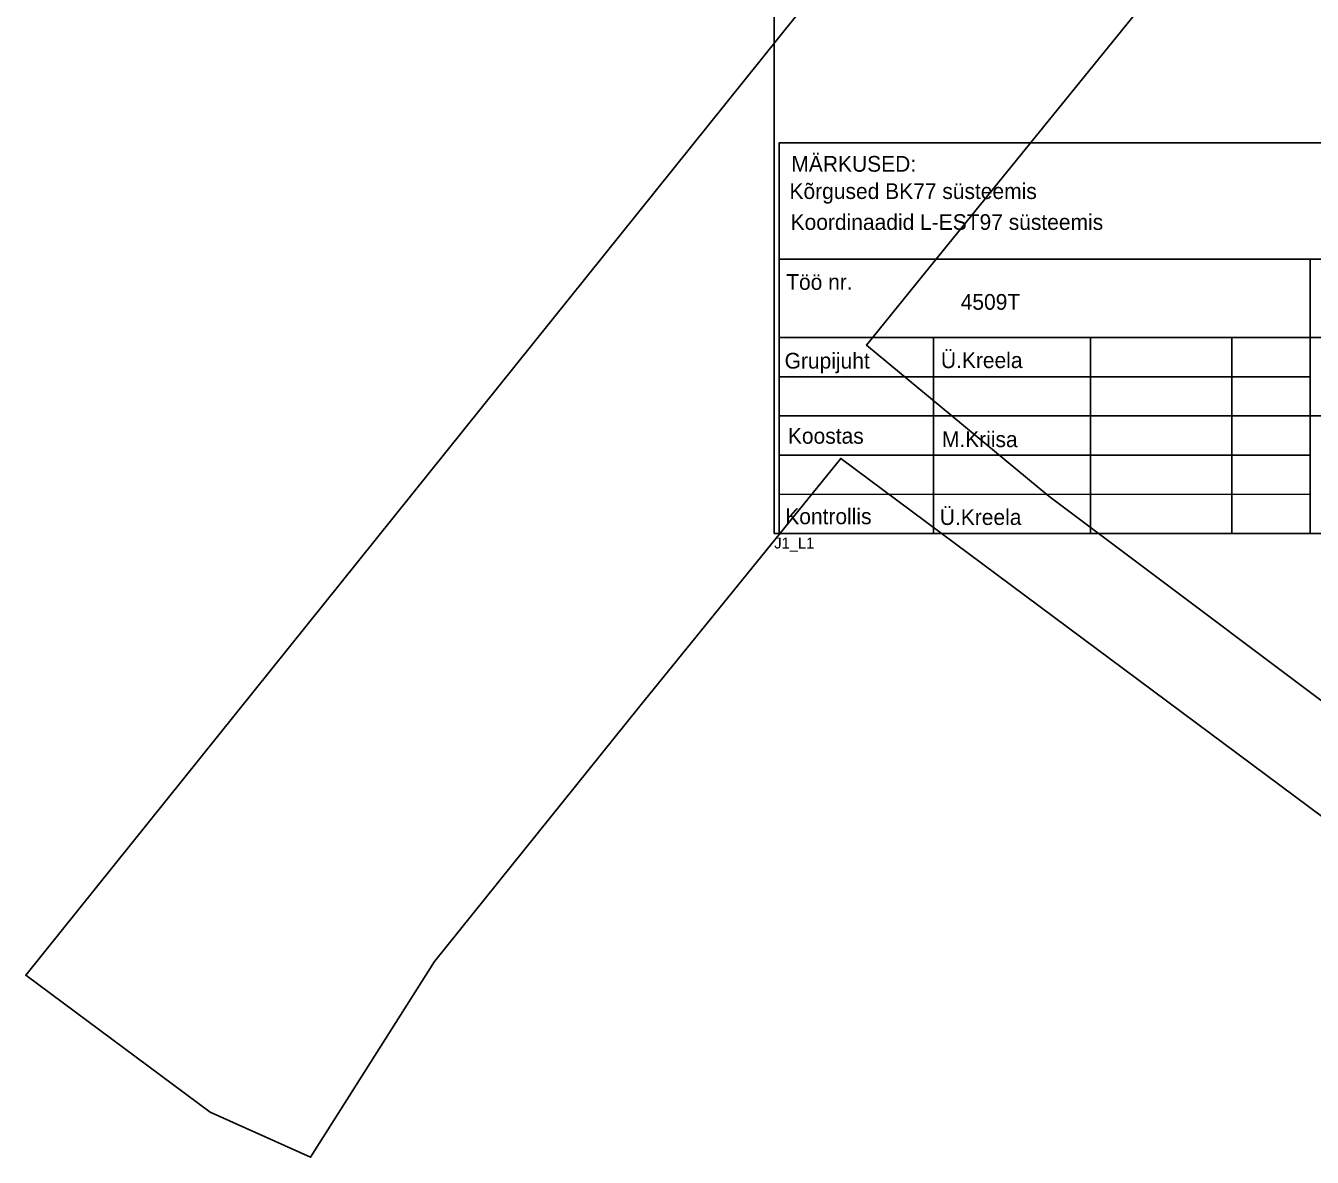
# Model space of a CAD drawing. Extents: x 640876 to 641182, y 6455704 to 6455993.
# Drawn here: x 640876.4 to 640958.4, y 6455746.4 to 6455818.5 of the extents above; entities that cross this region are included whole.
import ezdxf

# ---------------------------------------------------------------- set-up
doc = ezdxf.new("R2010")
doc.units = 0
doc.layers.add('PIIR', color=7, linetype='Continuous')
doc.layers.add('VORMISTUS', color=7, linetype='Continuous')

msp = doc.modelspace()

# ---------------------------------------------------------------- linework, layer by layer
at = {"layer": 'PIIR'}
msp.add_lwpolyline([(641037.5, 6455958.58), (641024.93, 6455943.02), (641012.36, 6455927.46), (640993.57, 6455904.12), (640971.01, 6455875.38), (640962.33, 6455865.02), (640876.41, 6455757.97), (640888.17, 6455749.25), (640894.56, 6455746.37), (640902.45, 6455758.84), (640915.55, 6455775.13), (640928.34, 6455790.92), (640960.9, 6455766.7), (640964.64, 6455771.22), (640941.6, 6455788.51), (640929.99, 6455798.13), (640933.13, 6455802.02), (640952.64, 6455826.1), (640977.72, 6455857.07), (640984.64, 6455865.92), (641005.01, 6455891.09), (641032.25, 6455870.2), (641049.71, 6455856.81)], dxfattribs=at)
at = {"layer": 'VORMISTUS'}
for p, q in [((640924.41, 6455803.627), (641016.602, 6455803.627)), ((640924.41, 6455803.627), (640924.416, 6455786.126)), ((640958.259, 6455803.62), (640958.262, 6455786.129)), ((640924.411, 6455798.631), (641016.602, 6455798.621)), ((640934.257, 6455798.63), (640934.262, 6455786.126)), ((640944.262, 6455798.624), (640944.264, 6455786.129)), ((640953.263, 6455798.623), (640953.256, 6455786.125)), ((640924.412, 6455796.128), (640958.258, 6455796.13)), ((640924.414, 6455793.625), (640991.762, 6455793.625)), ((640924.413, 6455791.132), (640958.261, 6455791.125)), ((640924.414, 6455788.629), (640958.26, 6455788.631)), ((640924.416, 6455786.126), (641016.602, 6455786.126))]:
    msp.add_line(p, q, dxfattribs=at)
for points in [[(640924.107, 6455786.126), (640924.107, 6455929.626), (641016.607, 6455929.626), (641016.607, 6455786.126)], [(641015.363, 6455786.126), (640924.416, 6455786.126), (640924.416, 6455811.035), (641015.363, 6455811.035)]]:
    msp.add_lwpolyline(points, close=True, dxfattribs=at)
msp.add_lwpolyline([(640924.416, 6455786.126), (641016.602, 6455786.126)], dxfattribs=at)

# ---------------------------------------------------------------- texts
for s, height, rotation, p in [('MÄRKUSED:', 1, 359.99461, (640925.197, 6455809.197)), ('Kõrgused BK77 süsteemis', 1.00002, 359.99461, (640925.077, 6455807.457)), ('Koordinaadid L-EST97 süsteemis ', 0.99996, 359.99461, (640925.147, 6455805.487)), ('Töö nr.', 0.9997, 359.99742, (640924.867, 6455801.667)), ('4509T', 0.9997, 359.99742, (640935.987, 6455800.397)), ('Grupijuht', 0.9997, 359.99742, (640924.767, 6455796.647)), ('Ü.Kreela', 0.9997, 359.99742, (640934.727, 6455796.677)), ('Koostas', 0.9997, 359.99742, (640924.977, 6455791.857)), ('M.Kriisa', 0.9997, 359.99742, (640934.787, 6455791.637)), (' Kontrollis', 0.99966, 359.99742, (640924.437, 6455786.727)), ('Ü.Kreela', 1, 359.99742, (640934.657, 6455786.677))]:
    msp.add_text(s, height=height, rotation=rotation, dxfattribs=at).set_placement(p)
msp.add_text('J1_L1', height=0.7, dxfattribs=at).set_placement((640924.107, 6455785.176))

doc.saveas('drawing.dxf')
